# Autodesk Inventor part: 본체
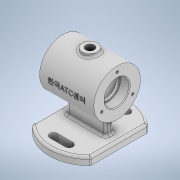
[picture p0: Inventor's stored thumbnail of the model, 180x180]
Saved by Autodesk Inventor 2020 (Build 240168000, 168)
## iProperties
Created: 2021-09
Part Number: 본체
Material: 일반
Document SubType Name: Modeling
Designer: Administrator
Density: 1 g/cm^3
Appearance: 기본값
Author: Administrator
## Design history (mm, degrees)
sketch "스케치1"
  geometry: L1 (37.5, -36.742)-(37.5, 36.742); L2 (-37.5, -36.742)-(-37.5, 36.742); L3 (37.5, 0)-(-37.5, 0); A1 r 52.5 centre (0, 0) between (37.5, 36.742) and (-37.5, 36.742); A2 r 52.5 centre (0, 0) between (-37.5, -36.742) and (37.5, -36.742); 2 further points
  constraints: 6 end point, 4 point on circle, 3 midpoint, 2 centre point, 2 coincident, 2 vertical
  dimensions: "d1" = 75 distance between parallel lines of L2 L1; "d60" = 52.5 radius of A2
extrude "돌출1" new body sketch "스케치1" distance "d2" = 10; taper "d3" = 0 deg
sketch "스케치2"
  geometry: C1 r 30 at (62, 0); 1 further point
  constraints: 1 centre point, 1 horizontal alignment
  dimensions: "d4" = 62 distance of C1.centre point (0, 0); "d11" = 60 diameter of C1
extrude "돌출2" join sketch "스케치2" stored distance "d5" = 70; taper "d6" = 0 deg
sketch "스케치3"
  geometry: L1 (62, 0)-(95, 0); C1 r 30 at (62, 0) reference; 1 further point
  constraints: 2 end point, 1 horizontal
  dimensions: "d7" = 33 distance of L1.start L1.end
node "작업 평면1"
sketch "스케치4"
  geometry: C1 r 10 at (0, 0); 2 further points
  constraints: 1 centre point, 1 coincident
  dimensions: "d8" = 20 diameter of C1
extrude "돌출3" join sketch "스케치4" stored distance "d9" = 70; taper "d10" = 0 deg
sketch "스케치5"
  geometry: C1 r 30 at (0, 0) reference; 2 further points
  constraints: 1 coincident
hole "구멍1" sketch "스케치5" at (0, 0) diameter "d12" = 28; stored, may be unused: countersink angle "d16" = 90 deg, drill point angle "d18" = 118 deg; dims "d13" = 6, "d14" = 32, "d15" = 12, "d17" = 8
sketch "스케치6"
  geometry: L1 (-23, 76)-(-23, 48) reference; L2 (-23, 62)-(23, 62); L3 (-20, 87)-(20, 87); L4 (-20, 87)-(-20, 62); L5 (20, 87)-(20, 62); 3 further points
  constraints: 8 end point, 3 midpoint, 2 horizontal, 2 perpendicular, 2 point on line, 1 vertical alignment
  dimensions: "d19" = 40 distance of L3.start L3.end; "d21" = 50 diameter of L3 L2
revolve "회전1" sketch "스케치6" stored, may be unused: angle "d22" = 90 deg
sketch "스케치7"
  geometry: L1 (-25, 35.562)-(25, 35.562); L2 (25, 35.562)-(25, 5.882); L3 (25, 5.882)-(-25, 5.882); L4 (-25, 5.882)-(-25, 35.562); L5 (-25, 35.562)-(25, 5.882); L6 (25, 35.562)-(-25, 5.882); L7 (-37.5, 0)-(-37.5, 10) reference; 2 further points
  constraints: 12 end point, 2 midpoint, 2 parallel, 1 horizontal, 1 perpendicular
  dimensions: "d23" = 50 distance of L2.end L3.end; "d24" = 12.5 distance between parallel lines of L4 L7
extrude "돌출4" join sketch "스케치7" stored distance "d25" = 10; taper "d26" = 0 deg
sketch "스케치8"
  geometry: C1 r 10 at (0, 0) reference; 2 further points
  constraints: 1 coincident
hole "구멍2" sketch "스케치8" at (0, 0) diameter "d27" = 10.917; stored, may be unused: countersink angle "d31" = 90 deg, drill point angle "d33" = 118 deg; dims "d28" = 24, "d29" = 32, "d30" = 12, "d32" = 29.1
sketch "스케치9"
  geometry: C1 r 30 at (0, 0) reference; 2 further points
  constraints: 1 vertical alignment
  dimensions: "d41" = 23 distance of C1.centre point (0, 23)
hole "구멍3" sketch "스케치9" at (0, 23) diameter "d34" = 3.242; stored, may be unused: countersink angle "d38" = 90 deg, drill point angle "d40" = 118 deg; dims "d35" = 8, "d36" = 32, "d37" = 12, "d39" = 10
fillet "모깎기1" dims "d45" = 0.3
fillet "모깎기2" dims "d46" = 3
fillet "모깎기3" dims "d47" = 3
chamfer "모따기1" distance "d48" = 1; stored, may be unused: second distance "d49" = 2, angle "d50" = 45 deg
sketch "스케치10"
  geometry: L1 (-10, 37)-(10, 37); L2 (-10, 32)-(10, 32); L3 (10, 42)-(-10, 42); A1 r 5 centre (-10, 37) between (-10, 42) and (-10, 32); A2 r 5 centre (10, 37) between (10, 32) and (10, 42); 2 further points
  constraints: 8 end point, 4 point on circle, 4 tangent, 2 centre point, 1 horizontal, 1 midpoint, 1 parallel, 1 vertical alignment
  dimensions: "d51" = 20 distance of L1.start L1.end; "d52" = 5 radius of A1; "d53" = 37 distance from line of point (0, 0) L1
extrude "돌출5" cut sketch "스케치10" extent not by distance; stored distance "d54" = 0; taper "d55" = 0 deg
node "작업 평면2"
sketch "스케치11"
  geometry: L1 (-35, 30)-(-35, -30) reference; L2 (-35, 30)-(35, 30) reference; 2 further points
  constraints: 1 other
  dimensions: "d56" = 35 distance from line of L1 point (0, 0); "d57" = 30 distance from line of point (0, 0) L2
feature "엠보싱1" sketch "스케치11" dims "d11" = 60, "d58" = 0.5, "d59" = 0
node "솔리드1"
mirror "미러1"
pattern_circular "원형 패턴1" dims angle "d43" = 360 deg
mirror "미러2"
mirror "미러3"
feature "A9D066F2-1C7D-4E18-AEED-F7BC21143FA4" dims "d12" = 28, "d13" = 6, "d14" = 32, "d15" = 12, "d16" = 90 deg, "d17" = 8, "d18" = 118 deg
other parameters: "d0" = 105
